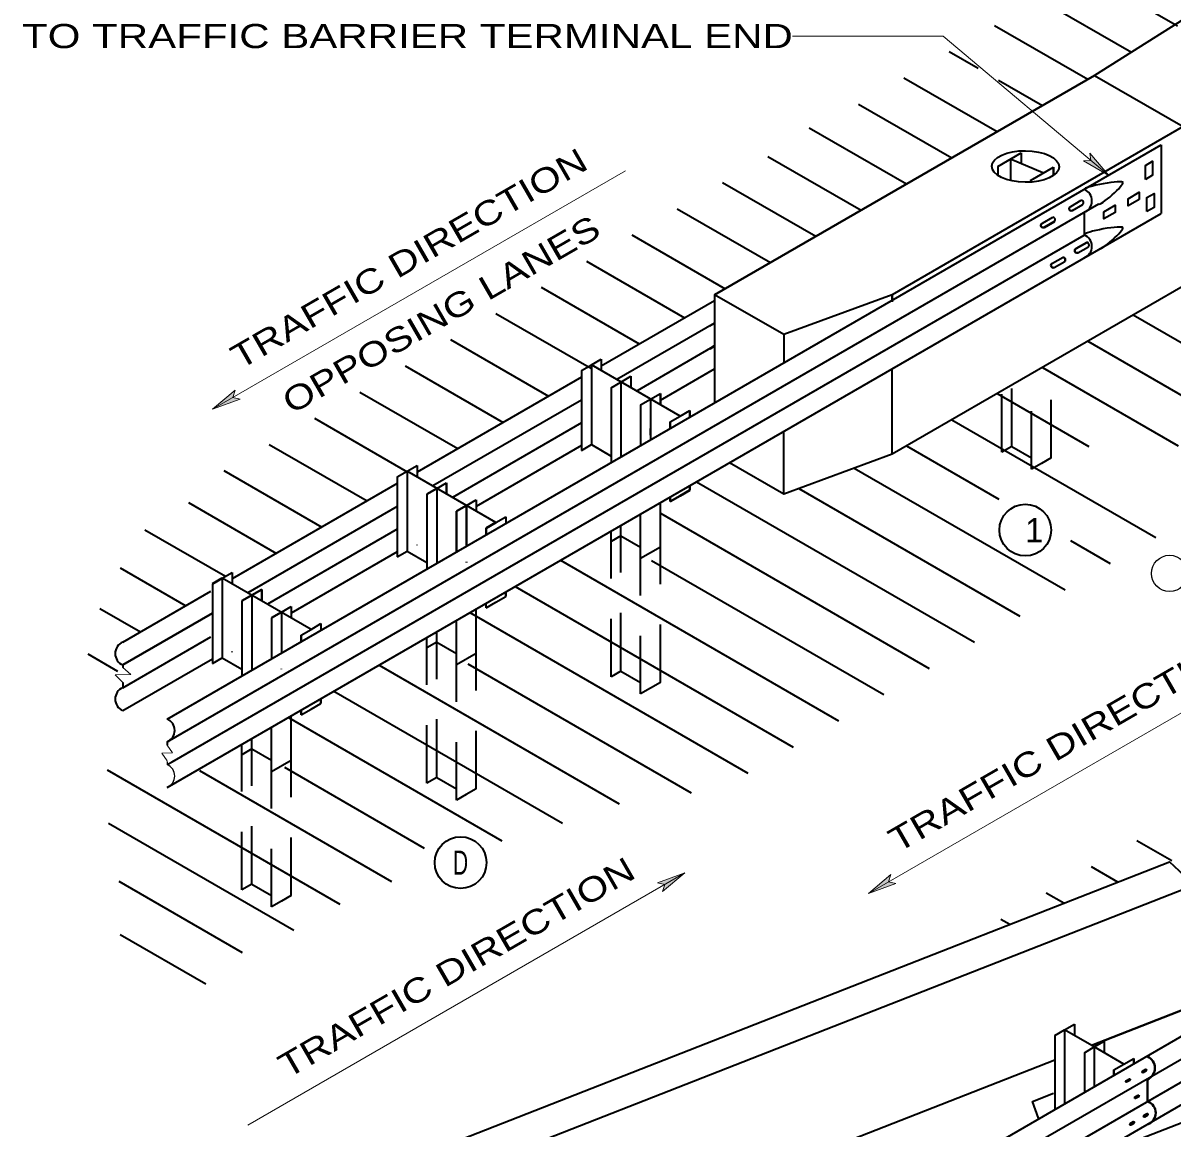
# Model space of a CAD drawing. Extents: x 12.4 to 19.52, y 6.05 to 15.92.
# Drawn here: x 12.404 to 15.254, y 9.379 to 12.12 of the extents above; entities that cross this region are included whole.
import ezdxf
from ezdxf.enums import TextEntityAlignment as Align

# ---------------------------------------------------------------- set-up
doc = ezdxf.new("R2010")
doc.units = 0
doc.header["$LTSCALE"] = 0.024
doc.linetypes.add('LONG_DASHED', pattern=[7.5, 6, -1.5])
for name, color, linetype, lineweight in [('1', 7, 'Continuous', 35), ('10', 7, 'Continuous', 13), ('12', 7, 'Continuous', 53)]:
    doc.layers.add(name, color=color, linetype=linetype, lineweight=lineweight)

msp = doc.modelspace()

# ---------------------------------------------------------------- hatches: boundary and pattern name
at = {"layer": '10'}
for points in [[(15.0508, 11.7975), (15.0973, 11.7418), (15.0345, 11.7783), (15.053, 11.7792)], [(12.9423, 11.1875), (12.8741, 11.1627), (12.9297, 11.2094), (12.9243, 11.1917)], [(13.9779, 9.9879), (14.0461, 10.0127), (13.9905, 9.966), (13.9959, 9.9837)], [(14.5694, 9.9861), (14.5012, 9.9613), (14.5568, 10.008), (14.5514, 9.9903)]]:
    msp.add_hatch(color=256, dxfattribs=at).paths.add_polyline_path(points)

# ---------------------------------------------------------------- linework, layer by layer
at = {"layer": '1'}
for p, q in [((16.2127, 12.714), (15.062, 11.9906)), ((15.2677, 12.1125), (15.0393, 12.2444)), ((14.9268, 12.1793), (15.1538, 12.0482)), ((14.8143, 12.1144), (15.0454, 11.981)), ((14.7018, 12.0494), (14.7733, 12.0082)), ((14.5893, 11.9845), (14.8204, 11.8511)), ((14.8243, 11.9787), (14.9329, 11.916)), ((14.4768, 11.9195), (14.7079, 11.7861)), ((14.354, 11.8605), (14.5954, 11.7212)), ((12.7613, 10.3938), (15.2279, 11.8179)), ((15.2279, 11.8179), (15.2279, 11.6483)), ((19.1506, 11.786), (12.649, 8.0324)), ((14.2518, 11.7896), (14.4829, 11.6562)), ((14.8224, 11.7649), (14.8804, 11.7984)), ((14.9342, 11.7484), (14.8537, 11.783)), ((14.8537, 11.783), (14.8537, 11.7307)), ((14.8804, 11.7984), (14.8804, 11.7718)), ((14.8224, 11.7649), (14.8224, 11.7434)), ((14.9031, 11.7299), (14.9602, 11.7629)), ((19.1513, 11.7299), (12.649, 7.9758)), ((14.1393, 11.7247), (14.3704, 11.5913)), ((14.9031, 11.7299), (14.9031, 11.7272)), ((19.1513, 11.6733), (12.649, 7.9193)), ((12.7613, 10.3373), (15.0726, 11.6717)), ((15.0032, 11.6656), (15.0292, 11.6806)), ((15.0073, 11.6552), (15.0334, 11.6702)), ((12.7613, 10.2243), (15.2279, 11.6483)), ((14.0268, 11.6597), (14.2579, 11.5263)), ((14.9329, 11.6237), (14.9588, 11.6387)), ((15.0368, 11.651), (15.0368, 11.5945)), ((13.9143, 11.5948), (14.1454, 11.4614)), ((15.021, 11.5506), (15.047, 11.5656)), ((13.8018, 11.5299), (14.0452, 11.3894)), ((14.9581, 11.5244), (14.984, 11.5394)), ((14.9622, 11.514), (14.9882, 11.529)), ((13.6893, 11.4649), (13.9326, 11.3244)), ((15.2822, 11.4677), (14.5602, 11.051)), ((13.8382, 11.27), (14.1197, 11.4324)), ((13.5768, 11.3999), (13.8138, 11.2631)), ((14.1197, 11.3759), (13.877, 11.2358)), ((15.1582, 11.3962), (15.5023, 11.1974)), ((14.291, 11.3477), (14.291, 11.2793)), ((13.4643, 11.335), (13.7076, 11.1945)), ((14.1197, 11.3194), (13.9274, 11.2084)), ((15.0457, 11.3312), (15.4161, 11.1173)), ((13.3518, 11.27), (13.5951, 11.1296)), ((13.7893, 11.2582), (13.8138, 11.2724)), ((13.8138, 11.2724), (13.8382, 11.2865)), ((14.034, 11.1451), (13.8138, 11.2724)), ((13.8138, 11.2724), (13.8138, 11.0745)), ((13.8382, 11.2865), (13.8382, 11.2572)), ((13.9851, 11.1851), (14.1197, 11.2628)), ((14.5602, 11.051), (14.5602, 11.2614)), ((14.9332, 11.2663), (15.27, 11.0718)), ((13.7893, 11.2417), (13.3813, 11.0062)), ((13.7893, 11.2582), (13.7893, 11.0603)), ((13.8871, 11.2299), (13.9117, 11.244)), ((13.9117, 11.244), (13.9117, 11.2168)), ((13.2393, 11.2051), (13.4826, 11.0646)), ((13.8627, 11.2158), (13.8871, 11.2299)), ((13.8627, 11.2158), (13.8627, 11.0297)), ((13.8871, 11.2299), (13.8871, 11.0438)), ((13.7893, 11.1851), (13.4201, 10.972)), ((13.9361, 11.1734), (13.9606, 11.1875)), ((13.9606, 11.1875), (13.9851, 11.2016)), ((13.9606, 11.1875), (13.9606, 11.0862)), ((14.8207, 11.2013), (15.0481, 11.0701)), ((13.9361, 11.1734), (13.9361, 11.0721)), ((14.034, 11.1451), (14.0585, 11.1593)), ((13.1268, 11.1401), (13.3569, 11.0072)), ((13.7893, 11.1287), (13.4691, 10.9437)), ((14.0095, 11.131), (14.034, 11.1451)), ((14.7082, 11.1364), (15.2144, 10.844)), ((14.291, 10.952), (14.291, 11.1059)), ((13.0143, 11.0752), (13.2576, 10.9348)), ((13.7893, 11.0721), (13.5282, 10.9214)), ((13.7893, 11.0603), (13.8138, 11.0745)), ((13.8138, 11.0745), (13.8627, 11.0462)), ((14.5957, 11.0714), (14.8244, 10.9394)), ((12.649, 8.0888), (17.757, 11.038)), ((12.9018, 11.0102), (13.1451, 10.8698)), ((13.3324, 10.9944), (13.3569, 11.0085)), ((13.3569, 11.0085), (13.3813, 11.0227)), ((13.5772, 10.8814), (13.3569, 11.0085)), ((13.3569, 11.0085), (13.3569, 10.8107)), ((13.3813, 11.0227), (13.3813, 10.9935)), ((14.4661, 11.0164), (14.9894, 10.7142)), ((13.3324, 10.9779), (12.9224, 10.7413)), ((13.3324, 10.9944), (13.3324, 10.7966)), ((13.4302, 10.9661), (13.4548, 10.9802)), ((14.0747, 10.9826), (14.7644, 10.5842)), ((13.4059, 10.952), (13.4059, 10.7659)), ((13.4302, 10.9661), (13.4302, 10.7801)), ((14.3287, 10.9658), (14.877, 10.6493)), ((12.8144, 10.9309), (13.0326, 10.8049)), ((13.3324, 10.9214), (12.9613, 10.7071)), ((13.5037, 10.9238), (13.5282, 10.9379)), ((13.5282, 10.9379), (13.5282, 10.9109)), ((13.985, 10.8202), (13.985, 10.9308)), ((13.5772, 10.8814), (13.6016, 10.8955)), ((13.6016, 10.8955), (13.6016, 10.879)), ((13.936, 10.792), (13.936, 10.9026)), ((13.9851, 10.9046), (14.652, 10.5194)), ((12.7058, 10.8636), (12.9058, 10.7481)), ((13.3324, 10.8648), (13.0102, 10.6788)), ((13.8872, 10.8484), (13.8872, 10.8744)), ((13.8872, 10.8484), (13.936, 10.8202)), ((15.1019, 10.7791), (15.0034, 10.836)), ((13.3324, 10.8083), (13.0693, 10.6564)), ((13.3324, 10.7966), (13.3569, 10.8107)), ((13.3569, 10.8107), (13.4059, 10.7825)), ((13.3813, 10.8248), (13.3813, 10.826)), ((13.985, 10.8202), (13.936, 10.792)), ((13.7372, 10.7877), (14.427, 10.3895)), ((13.9629, 10.7873), (14.5395, 10.4544)), ((12.6446, 10.769), (12.8076, 10.6749)), ((12.898, 10.7436), (12.9224, 10.7577)), ((12.9224, 10.7577), (12.9224, 10.7285)), ((12.8735, 10.7294), (12.8735, 10.5316)), ((13.1183, 10.6164), (12.898, 10.7436)), ((12.898, 10.7436), (12.898, 10.5458)), ((13.6247, 10.7228), (14.3146, 10.3245)), ((12.6512, 10.5846), (12.8699, 10.7109)), ((12.9715, 10.7012), (12.9715, 10.5151)), ((12.5942, 10.6682), (12.6952, 10.61)), ((12.9469, 10.6871), (12.9469, 10.5011)), ((13.0448, 10.6588), (13.0693, 10.673)), ((13.0693, 10.673), (13.0693, 10.646)), ((13.5282, 10.5564), (13.5282, 10.667)), ((13.5527, 10.6694), (13.5527, 10.6801)), ((13.0204, 10.6447), (13.0204, 10.5434)), ((13.0448, 10.6588), (13.0448, 10.5575)), ((13.4792, 10.5282), (13.4792, 10.6388)), ((13.5122, 10.6579), (14.202, 10.2596)), ((13.0938, 10.6023), (13.1183, 10.6164)), ((13.1183, 10.6164), (13.1427, 10.6305)), ((13.1427, 10.6305), (13.1427, 10.6141)), ((13.4303, 10.5846), (13.4303, 10.6106)), ((12.6512, 10.4716), (12.8699, 10.5979)), ((13.4303, 10.5846), (13.4792, 10.5564)), ((12.5648, 10.5553), (12.6382, 10.5129)), ((12.9224, 10.5599), (12.9224, 10.5611)), ((13.5282, 10.5564), (13.4792, 10.5282)), ((12.6512, 10.415), (12.8735, 10.5434)), ((12.6512, 10.5284), (12.6512, 10.5221)), ((12.8735, 10.5316), (12.898, 10.5458)), ((12.898, 10.5458), (12.9469, 10.5175)), ((13.2872, 10.5279), (13.8832, 10.1838)), ((13.507, 10.531), (14.0614, 10.2108)), ((13.0448, 10.5175), (13.0448, 10.5186)), ((12.6512, 10.4848), (12.6512, 10.4716)), ((13.1747, 10.463), (13.7422, 10.1354)), ((13.0621, 10.398), (13.5921, 10.092)), ((13.0693, 10.2914), (13.0693, 10.4021)), ((13.0203, 10.2632), (13.0203, 10.3738)), ((12.7613, 10.3373), (12.7735, 10.3444)), ((12.7613, 10.3373), (12.7613, 10.3287)), ((12.9469, 10.3055), (12.9469, 10.3314)), ((12.9714, 10.3197), (12.9714, 10.3456)), ((12.9714, 10.3197), (12.9469, 10.3055)), ((12.9714, 10.3197), (13.0203, 10.2915)), ((13.0693, 10.2914), (13.0203, 10.2632)), ((12.6124, 10.268), (13.1895, 9.935)), ((12.8413, 10.2659), (13.3179, 9.9906)), ((13.4002, 10.073), (13.053, 10.2735)), ((12.6161, 10.136), (13.076, 9.8705)), ((15.2539, 10.0418), (15.1673, 10.0919)), ((13.3674, 9.3032), (15.248, 10.0395)), ((15.31, 9.9818), (15.248, 10.0395)), ((15.1199, 9.9893), (15.0548, 10.0269)), ((12.6413, 9.9916), (12.9476, 9.8147)), ((15.31, 9.9818), (13.4295, 9.2454)), ((14.9859, 9.9368), (14.9423, 9.962)), ((14.8517, 9.8843), (14.8298, 9.897)), ((12.645, 9.8595), (12.8575, 9.7368)), ((14.988, 9.6229), (15.0124, 9.6371)), ((15.0124, 9.6371), (15.0124, 9.6098)), ((14.9635, 9.6088), (14.988, 9.6229)), ((14.9635, 9.6088), (14.9635, 9.4251)), ((14.988, 9.6229), (14.988, 9.4392)), ((15.037, 9.5663), (15.0614, 9.5804)), ((15.0614, 9.5804), (15.0859, 9.5946)), ((15.0614, 9.5804), (15.0614, 9.4816)), ((15.0859, 9.5946), (15.0859, 9.5663)), ((15.037, 9.5663), (15.037, 9.4674)), ((15.1348, 9.5381), (15.1593, 9.5522)), ((13.4515, 8.9566), (14.9635, 9.5486)), ((15.1103, 9.524), (15.1348, 9.5381)), ((15.1103, 9.524), (15.1348, 9.5381)), ((15.1367, 9.3374), (15.4043, 9.4423))]:
    msp.add_line(p, q, dxfattribs=at)
at = {"layer": '1', "lineweight": 40}
for p, q in [((15.062, 11.9906), (14.1197, 11.4465)), ((14.9602, 11.7629), (14.9602, 11.745)), ((14.937, 11.6133), (14.963, 11.6283)), ((15.0169, 11.561), (15.0428, 11.576)), ((14.5602, 11.4465), (14.5602, 11.4289)), ((14.1197, 11.3759), (14.1074, 11.3689)), ((14.1197, 11.3194), (14.1074, 11.3123)), ((13.9851, 11.2016), (13.9851, 11.1734)), ((14.0585, 11.1593), (14.0585, 11.1428)), ((14.0095, 11.131), (14.0095, 11.1145)), ((13.9603, 11.1146), (13.9603, 11.0981)), ((13.7889, 11.0722), (13.7889, 11.0734)), ((13.4548, 10.9802), (13.4548, 10.9531)), ((13.4059, 10.952), (13.4302, 10.9661)), ((14.0585, 10.9615), (14.0585, 10.9738)), ((13.4793, 10.9097), (13.5037, 10.9238)), ((13.5037, 10.9238), (13.5037, 10.8224)), ((14.0095, 10.9331), (14.0095, 10.9439)), ((13.4793, 10.9097), (13.4793, 10.8083)), ((13.5527, 10.8672), (13.5772, 10.8814)), ((13.5527, 10.8672), (13.5527, 10.8508)), ((13.5037, 10.7825), (13.5037, 10.7837)), ((12.8735, 10.7294), (12.898, 10.7436)), ((12.9469, 10.6871), (12.9715, 10.7012)), ((12.9715, 10.7012), (12.9959, 10.7153)), ((12.9959, 10.7153), (12.9959, 10.6881)), ((13.6016, 10.6976), (13.6016, 10.71)), ((12.6517, 10.5284), (12.8735, 10.6564)), ((13.0204, 10.6447), (13.0448, 10.6588)), ((13.0938, 10.6023), (13.0938, 10.5857)), ((13.1427, 10.4327), (13.1427, 10.4451)), ((13.0938, 10.4045), (13.0938, 10.4152)), ((15.3322, 9.6929), (15.0548, 9.5843)), ((15.0859, 9.5663), (15.0859, 9.5653)), ((15.1593, 9.5522), (15.1593, 9.5381)), ((15.1103, 9.524), (15.1103, 9.5099)), ((15.1893, 9.5245), (15.1809, 9.5197)), ((15.1823, 9.5172), (15.1907, 9.522)), ((15.1103, 9.5099), (15.1103, 9.5094)), ((15.1486, 9.5009), (15.1402, 9.496)), ((15.1417, 9.4936), (15.1501, 9.4984)), ((15.1939, 9.5), (15.1939, 9.4452)), ((15.1706, 9.4604), (15.1623, 9.4555)), ((15.1637, 9.4531), (15.172, 9.4579)), ((15.1927, 9.4148), (15.1843, 9.4099)), ((15.1858, 9.4075), (15.1941, 9.4123)), ((15.1588, 9.3945), (15.1504, 9.3896)), ((15.1519, 9.3872), (15.1602, 9.392))]:
    msp.add_line(p, q, dxfattribs=at)
at = {"layer": '1', "linetype": 'LONG_DASHED'}
for p, q in [((14.955, 11.0418), (14.955, 11.2789)), ((14.906, 11.0136), (14.906, 11.2506)), ((14.8326, 11.0558), (14.8326, 11.2082)), ((14.8572, 11.07), (14.8572, 11.2224)), ((14.8572, 11.07), (14.8326, 11.0558)), ((14.857, 11.07), (14.906, 11.0418)), ((14.955, 11.0418), (14.9304, 11.0276)), ((14.9304, 11.0276), (14.906, 11.0136)), ((13.8626, 10.4988), (13.8626, 10.8342)), ((13.8872, 10.513), (13.8872, 10.8484)), ((13.985, 10.4848), (13.985, 10.8202)), ((13.936, 10.4566), (13.936, 10.792)), ((13.4303, 10.2492), (13.4303, 10.5846)), ((13.4058, 10.235), (13.4058, 10.5704)), ((13.5282, 10.221), (13.5282, 10.5564)), ((13.4792, 10.1928), (13.4792, 10.5282)), ((13.8872, 10.513), (13.8626, 10.4988)), ((13.887, 10.513), (13.936, 10.4848)), ((13.9604, 10.4706), (13.936, 10.4566)), ((13.985, 10.4848), (13.9604, 10.4706)), ((12.9469, 9.9701), (12.9469, 10.3055)), ((12.9714, 9.9843), (12.9714, 10.3197)), ((13.0693, 9.956), (13.0693, 10.2914)), ((13.0203, 9.9278), (13.0203, 10.2632)), ((13.4303, 10.2492), (13.4058, 10.235)), ((13.4302, 10.2492), (13.4792, 10.221)), ((13.5036, 10.2068), (13.4792, 10.1928)), ((13.5282, 10.221), (13.5036, 10.2068)), ((12.9714, 9.9843), (12.9469, 9.9701)), ((12.9713, 9.9843), (13.0203, 9.956)), ((13.0693, 9.956), (13.0447, 9.9419)), ((13.0447, 9.9419), (13.0203, 9.9278))]:
    msp.add_line(p, q, dxfattribs=at)
at = {"layer": '1', "lineweight": 25}
msp.add_line((12.7613, 10.2882), (12.7613, 10.2808), dxfattribs=at)
at = {"layer": '1'}
for points in [[(15.062, 11.9906), (15.2822, 11.8634), (14.5602, 11.4465), (14.291, 11.3477)], [(12.7613, 10.2808), (12.7735, 10.2878), (15.0368, 11.5945)], [(14.291, 11.3477), (14.1197, 11.4465), (14.1197, 11.1798)], [(14.5602, 11.051), (14.291, 10.952), (14.1564, 11.0297)], [(13.8872, 10.8484), (13.8626, 10.8342), (13.8626, 10.8602)], [(13.5527, 10.6694), (13.5772, 10.6835), (13.6016, 10.6976)], [(13.4303, 10.5846), (13.4058, 10.5704), (13.4058, 10.5964)], [(13.0938, 10.4045), (13.1183, 10.4186), (13.1427, 10.4327)], [(15.1348, 9.5381), (15.0615, 9.5805), (14.988, 9.6229)], [(14.923, 9.404), (14.9086, 9.4453), (14.9605, 9.4656)]]:
    msp.add_lwpolyline(points, dxfattribs=at)
for points in [[(15.1885, 11.7326), (15.1885, 11.7672), (15.2064, 11.7776), (15.2064, 11.7428)], [(15.1732, 11.6829), (15.1453, 11.6668), (15.1453, 11.6843), (15.1732, 11.7005)], [(15.1921, 11.6527), (15.1921, 11.6875), (15.2101, 11.6978), (15.2101, 11.663)], [(15.0853, 11.6522), (15.1133, 11.6683), (15.1133, 11.6508), (15.0853, 11.6347)]]:
    msp.add_lwpolyline(points, close=True, dxfattribs=at)
at = {"layer": '1', "lineweight": 40}
msp.add_lwpolyline([(14.0095, 10.9331), (14.034, 10.9473), (14.0585, 10.9615)], dxfattribs=at)
at = {"layer": '1'}
for centre, radius, start, end in [((15.02502, 11.6793), 0.0306, 292.56091, 67.43909), ((15.02861, 11.67436), 0.0063, 318.84925, 84.68249), ((14.95826, 11.63251), 0.0063, 318.84925, 84.68249), ((15.02502, 11.56626), 0.0306, 292.56091, 67.43909), ((15.04226, 11.56977), 0.0063, 318.84925, 84.68249), ((12.66294, 10.55635), 0.0306, 112.56091, 247.43909), ((12.66294, 10.4433), 0.0306, 112.56091, 247.43909), ((12.74959, 10.36559), 0.0306, 292.56091, 67.43909)]:
    msp.add_arc(centre, radius, start, end, dxfattribs=at)
at = {"layer": '1', "lineweight": 40}
for centre, radius, start, end in [((15.00484, 11.66024), 0.00563, 106.87657, 296.65516), ((14.93449, 11.61839), 0.00563, 106.87657, 296.65516), ((15.01849, 11.55565), 0.00563, 106.87657, 296.65516), ((14.95969, 11.51905), 0.00563, 106.87657, 296.65516), ((14.98346, 11.53317), 0.0063, 318.84925, 84.68249), ((15.18151, 9.52818), 0.0306, 292.56091, 67.43909), ((15.18985, 9.52322), 0.00143, 306.009, 113.99099), ((15.14112, 9.49489), 0.00143, 126.00901, 293.99099), ((15.1492, 9.49956), 0.00143, 306.009, 113.99099), ((15.18177, 9.51855), 0.00143, 126.00901, 293.99099), ((15.16313, 9.45439), 0.00143, 126.00901, 293.99099), ((15.17122, 9.45906), 0.00143, 306.009, 113.99099), ((15.18335, 9.41691), 0.0306, 292.56091, 67.43909), ((15.18518, 9.40879), 0.00143, 126.00901, 293.99099), ((15.19327, 9.41346), 0.00143, 306.009, 113.99099), ((15.15128, 9.38854), 0.00143, 126.00901, 293.99099), ((15.15937, 9.39321), 0.00143, 306.009, 113.99099)]:
    msp.add_arc(centre, radius, start, end, dxfattribs=at)
at = {"layer": '1', "lineweight": 25}
msp.add_arc((12.74959, 10.25254), 0.0306, 292.56091, 67.43909, dxfattribs=at)
at = {"layer": '1'}
msp.add_ellipse((14.89062, 11.76449), major_axis=(0.08358, -0.00086), ratio=0.468129, dxfattribs=at)
for centre, major_axis, ratio, start_param, end_param in [((15.08492, 11.71619), (0.04817, 0.00862), 0.113085, 0, 3.1415926), ((15.10231, 11.69826), (0.02975, 0.02655), 0.146286, 3.1415927, 6.2831853), ((15.08492, 11.60413), (0.04817, 0.00862), 0.113085, 0, 3.1415926), ((15.10231, 11.58621), (0.02975, 0.02655), 0.146286, 3.1415927, 6.2831853)]:
    msp.add_ellipse(centre, major_axis=major_axis, ratio=ratio, start_param=start_param, end_param=end_param, dxfattribs=at)
at = {"layer": '10'}
for p, q in [((14.3132, 12.0881), (14.6869, 12.0881)), ((14.6869, 12.0881), (15.0973, 11.7418)), ((15.0973, 11.7418), (15.0345, 11.7783)), ((15.0973, 11.7418), (15.0508, 11.7975)), ((12.8741, 11.1627), (13.8981, 11.7539)), ((12.8741, 11.1627), (12.9297, 11.2094)), ((12.8741, 11.1627), (12.9423, 11.1875)), ((14.5012, 9.9613), (15.5352, 10.5583)), ((12.9618, 9.3867), (14.0461, 10.0127)), ((14.0461, 10.0127), (13.9779, 9.9879)), ((14.0461, 10.0127), (13.9905, 9.966)), ((14.5012, 9.9613), (14.5568, 10.008)), ((14.5012, 9.9613), (14.5694, 9.9861))]:
    msp.add_line(p, q, dxfattribs=at)
for points in [[(15.0508, 11.7975), (15.053, 11.7792), (15.0345, 11.7783)], [(12.9423, 11.1875), (12.9243, 11.1917), (12.9297, 11.2094)], [(12.6512, 10.5221), (12.6709, 10.5041), (12.6324, 10.5035), (12.6512, 10.4848)], [(12.7613, 10.3287), (12.7748, 10.31), (12.7485, 10.3094), (12.7613, 10.29)], [(14.5694, 9.9861), (14.5514, 9.9903), (14.5568, 10.008)], [(13.9779, 9.9879), (13.9959, 9.9837), (13.9905, 9.966)]]:
    msp.add_lwpolyline(points, dxfattribs=at)
for points in [[(15.0508, 11.7975), (15.0973, 11.7418), (15.0345, 11.7783), (15.053, 11.7792)], [(12.9423, 11.1875), (12.8741, 11.1627), (12.9297, 11.2094), (12.9243, 11.1917)], [(13.9779, 9.9879), (14.0461, 10.0127), (13.9905, 9.966), (13.9959, 9.9837)], [(14.5694, 9.9861), (14.5012, 9.9613), (14.5568, 10.008), (14.5514, 9.9903)]]:
    msp.add_lwpolyline(points, close=True, dxfattribs=at)
at = {"layer": '10', "lineweight": 35}
for centre in [(14.8904, 10.86253), (13.48937, 10.03772)]:
    msp.add_circle(centre, 0.06414, dxfattribs=at)
at = {"layer": '10', "lineweight": 25}
msp.add_circle((15.24846, 10.75501), 0.04507, dxfattribs=at)

# ---------------------------------------------------------------- texts
at = {"layer": '12', "width": 1.3}
msp.add_text('TO TRAFFIC BARRIER TERMINAL END', height=0.06, dxfattribs=at).set_placement((12.4013, 12.0581))
at = {"layer": '12', "width": 1.25}
for s, p in [('TRAFFIC DIRECTION', (13.3761, 11.51018)), ('OPPOSING LANES', (13.4561, 11.37163)), ('TRAFFIC DIRECTION', (15.0082, 10.31168)), ('TRAFFIC DIRECTION', (13.494, 9.75158))]:
    msp.add_text(s, height=0.06, rotation=30, dxfattribs=at).set_placement(p, align=Align.CENTER)
at = {"layer": '12'}
msp.add_text('1', height=0.06, dxfattribs=at).set_placement((14.91281, 10.8324), align=Align.CENTER)
at = {"layer": '12', "width": 0.65}
msp.add_text('D', height=0.06, dxfattribs=at).set_placement((13.4893, 10.0077), align=Align.CENTER)

doc.saveas('drawing.dxf')
